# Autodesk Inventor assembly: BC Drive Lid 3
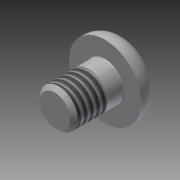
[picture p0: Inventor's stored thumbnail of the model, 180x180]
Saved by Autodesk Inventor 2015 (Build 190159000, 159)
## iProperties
Created: 2007-02
Part Number: BC Drive Lid 3
Document SubType Name: Assembly
Designer: Autodesk, Inc.
Mass: 1.89148 g
Surface Area: 2.92112 cm^2
Volume: 0.240646 cm^3
Density: 7.86 g/cm^3
ClientObjectVersion: 1
Author: Autodesk, Inc.
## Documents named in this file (2)
- C:\Users\Public\Documents\Autodesk\Inventor 2015\Samples\Models\Assemblies\Blower\Blower\Design Accelerator\BC Drive Lid 21.iam
- C:\Users\Public\Documents\Autodesk\Inventor 2015\Samples\Standard Parts\en-US\ANSI B18.3(03)\ANSI B18.3 - 10-32 UNF - UNF - 0.25(1).ipt
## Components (1 placed, 1 different names)
1. ANSI B18.3 - No. 10-32 - 1/4:1
